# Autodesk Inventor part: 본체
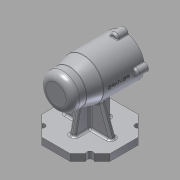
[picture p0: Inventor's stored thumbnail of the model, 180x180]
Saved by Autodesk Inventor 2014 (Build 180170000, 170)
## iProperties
Created: 2021-01
Part Number: 본체
Material: Aluminum 6061
Document SubType Name: Modeling
Designer: kh
Density: 2.71 g/cm^3
Appearance: Aluminum - Flat
Mass: 632.295 g
Surface Area: 613.777 cm^2
Volume: 233.319 cm^3
Author: kh
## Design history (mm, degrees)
sketch "Sketch1" dims "d0" = 100
  geometry: L1 (20.711, 50)-(50, 20.711); L2 (50, 20.711)-(50, -20.711); L3 (50, -20.711)-(20.711, -50); L4 (20.711, -50)-(-20.711, -50); L5 (-20.711, -50)-(-50, -20.711); L6 (-50, -20.711)-(-50, 20.711); L7 (-50, 20.711)-(-20.711, 50); L8 (-20.711, 50)-(20.711, 50); 4 further points
  constraints: 16 end point, 2 coincident, 1 horizontal, 1 midpoint, 1 vertical alignment, 19 other
extrude "Extrusion1" new body sketch "Sketch1" distance "d1" = 10; taper "d2" = 0 deg
sketch "Sketch2"
  geometry: L1 (-50, 75)-(50, 75); L2 (50, 75)-(50, 105); L3 (50, 105)-(-10, 105); L4 (-10, 105)-(-30, 100); L5 (-30, 100)-(-50, 100); L6 (-50, 100)-(-50, 75); L7 (50, 96)-(35, 96); L8 (35, 96)-(35, 99); L9 (35, 99)-(-7, 99); L10 (-7, 99)-(-7, 96); L11 (-7, 96)-(-19, 96); L12 (-19, 96)-(-19, 92.5); L13 (-19, 92.5)-(-37, 92.5); L14 (-37, 92.5)-(-37, 91); L15 (-37, 91)-(-41, 91); L16 (-41, 91)-(-41, 85.5); L17 (-41, 85.5)-(-44, 85.5); L18 (-44, 85.5)-(-44, 75); L19 (50, 0)-(50, 10) reference; 1 further point
  constraints: 36 end point, 11 parallel, 4 perpendicular, 2 collinear, 2 point on line, 1 horizontal
  dimensions: "d3" = 75 vertical distance of point (0, 0) L1.end; "d4" = 60 diameter of L3 L1; "d5" = 100 distance between parallel lines of L2 L6; "d6" = 20 distance from line of L4.end L6; "d7" = 40 horizontal distance of L3.end L5.end; "d8" = 50 diameter of L5 L1; "d9" = 15 distance of L7.start L7.end; "d10" = 3 distance of L16.end L17.end; "d11" = 4 distance of L14.end L15.end; "d12" = 18 distance of L12.end L13.end; "d13" = 12 distance of L10.end L11.end; "d14" = 42 distance of L8.end L9.end; "d15" = 42 diameter of L7 L1; "d16" = 48 diameter of L9 L1; "d17" = 42 diameter of L11 L1; "d18" = 21 diameter of L17 L1; "d19" = 32 diameter of L15 L1; "d20" = 35 diameter of L13 L1
revolve "Revolution1" sketch "Sketch2" stored, may be unused: angle "d21" = 90 deg
sketch "Sketch3"
  geometry: L1 (50, 10)-(20.711, 10) reference; L2 (27, 10)-(27, 32.649); 1 further point
  constraints: 2 end point, 1 perpendicular, 1 point on line
  dimensions: "d22" = 23 distance of L1.start L2.start
feature "Rib1" sketch "Sketch3" dims "d23" = 1, "d24" = 8, "d25" = 0, "d26" = 0, "d27" = 1, "d28" = 1
sketch "Sketch4"
  geometry: L1 (-20.711, 10)-(-50, 10) reference; L2 (20.711, 10)-(-20.711, 10) reference; L3 (-27, 10)-(-21.326, 39.189); 1 further point
  constraints: 2 end point, 1 point on line
  dimensions: "d29" = 101 deg angle of L1 L3; "d30" = 23 distance of L1.end L3.start
feature "Rib2" sketch "Sketch4" dims "d31" = 1, "d32" = 8, "d33" = 0, "d34" = 0, "d35" = 1, "d36" = 1
sketch "Sketch5"
  geometry: L1 (50, 10)-(20.711, 10) reference; L2 (-20.711, 10)-(-50, 10) reference; L3 (-35, 10)-(-25.925, 34.933); L4 (35, 10)-(27.063, 31.806); 1 further point
  constraints: 4 end point, 2 point on line
  dimensions: "d37" = 15 distance of L1.start L4.start; "d38" = 110 deg angle of L1 L4; "d39" = 15 distance of L2.end L3.start; "d40" = 110 deg angle of L2 L3
feature "Rib3" dims "d41" = 1, "d42" = 8, "d43" = 0, "d44" = 0, "d45" = 1, "d46" = 1
feature "Rib4" dims "d47" = 1, "d48" = 8, "d49" = 0, "d50" = 0, "d51" = 1, "d52" = 1
sketch "Sketch6"
  geometry: L1 (0, 0)-(0, -30); C1 r 6 at (0, -30); 1 further point
  constraints: 2 end point, 1 centre point, 1 coincident, 1 vertical, 1 vertical alignment, 1 other
  dimensions: "d53" = 12 diameter of C1
extrude "Extrusion2" join sketch "Sketch6" distance "d54" = 16; taper "d55" = 0 deg
hole "Hole1" diameter "d58" = 3.242; stored, may be unused: countersink angle "d62" = 90 deg, drill point angle "d64" = 118 deg; dims "d56" = 10, "d57" = 10, "d59" = 8, "d60" = 4, "d61" = 2, "d63" = 10
pattern_circular "Circular Pattern1" dims angle "d66" = 360 deg
fillet "Fillet1" dims "d68" = 3
fillet "Fillet2" dims "d69" = 3
fillet "Fillet3" dims "d70" = 10
fillet "Fillet4" dims "d71" = 1
fillet "Fillet5" dims "d72" = 3
fillet "Fillet6" dims "d73" = 3
fillet "Fillet7" dims "d74" = 3
fillet "Fillet8" dims "d75" = 0.3
fillet "Fillet9" dims "d76" = 3
chamfer "Chamfer1" distance "d77" = 1; stored, may be unused: second distance "d78" = 2, angle "d79" = 45 deg
sketch "Sketch7"
  geometry: L1 (-20.711, -50)-(-50, -20.711) reference; L2 (0, 0)-(-35.355, -35.355); C1 r 4.5 at (-35.355, -35.355)
  constraints: 2 end point, 1 centre point, 1 coincident, 1 midpoint
  dimensions: "d80" = 9 diameter of C1
extrude "Extrusion3" cut sketch "Sketch7" stored distance "d81" = 16; taper "d82" = 0 deg
pattern_circular "Circular Pattern2" dims angle "d84" = 360 deg
workplane "Work Plane1"
sketch "Sketch8"
  geometry: L1 (-24.592, 2.402)-(8.592, 2.402); L2 (8.592, 2.402)-(8.592, -2.402); L3 (8.592, -2.402)-(-24.592, -2.402); L4 (-24.592, -2.402)-(-24.592, 2.402); L5 (-24.592, 2.402)-(8.592, -2.402); L6 (30, 6.771)-(30, 29.226) reference; L7 (30, 5.998)-(30, -5.998) reference; L8 (30, -29.226)-(30, -6.771) reference; L9 (-70, -15)-(-70, 15) reference; 3 further points
  constraints: 2 end point, 2 midpoint, 1 horizontal alignment, 2 other
  dimensions: "d86" = 38 distance from line of L6 point (-8, 0)
emboss "Emboss1" sketch "Sketch8" dims "d3" = 75, "d4" = 60, "d5" = 100, "d6" = 20, "d7" = 40, "d8" = 50, "d9" = 15, "d10" = 3, "d11" = 4, "d12" = 18, "d13" = 12, "d14" = 42, "d15" = 42, "d16" = 48, "d17" = 42, "d18" = 21, "d19" = 32, "d20" = 35, "d87" = 0.5, "d88" = 0
body "Solid1"
